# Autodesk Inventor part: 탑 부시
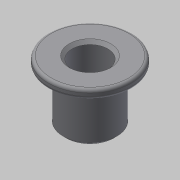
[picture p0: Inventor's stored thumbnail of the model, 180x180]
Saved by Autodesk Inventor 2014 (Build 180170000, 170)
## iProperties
Created: 2016-08
Part Number: 탑 부시
Material: 스테인리스강
Document SubType Name: Modeling
Designer: mduedu
Density: 8.08 g/cm^3
Appearance: Default
Author: mduedu
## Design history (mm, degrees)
sketch "스케치1"
  geometry: L1 (0, 0)-(9, 0); L2 (9, 0)-(9, 17); L3 (0, 20)-(0, 0); L4 (9, 17)-(14, 17); L5 (14, 17)-(14, 20); L6 (14, 20)-(0, 20)
  constraints: 12 end point, 2 horizontal, 2 parallel, 2 perpendicular
  dimensions: "d0" = 9 distance between parallel lines of L2 L3; "d2" = 20 distance of L3.start L1.start; "d3" = 14 distance between parallel lines of L5 L3; "d4" = 3 distance of L4.end L5.end
revolve "회전1" sketch "스케치1" stored, may be unused: angle "d5" = 90 deg
hole "구멍1" diameter "d8" = 12; stored, may be unused: countersink angle "d12" = 90 deg, drill point angle "d14" = 118 deg; dims "d6" = 10, "d7" = 10, "d9" = 6, "d10" = 4, "d11" = 2, "d13" = 8
chamfer "모따기1" distance "d15" = 1; stored, may be unused: second distance "d16" = 2, angle "d17" = 45 deg
fillet "모깎기1" dims "d18" = 1
node "솔리드1"
